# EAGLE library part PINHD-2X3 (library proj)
2mm PIN HEADER
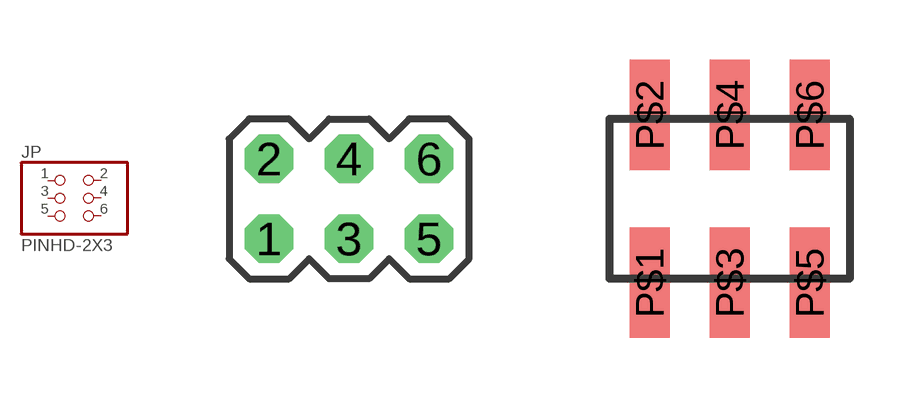
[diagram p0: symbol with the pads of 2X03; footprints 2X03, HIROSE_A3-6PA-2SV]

Designator prefix JP

## PINHD-2X3THRU  [2X03]
1  1  pas
2  2  pas
3  3  pas
4  4  pas
5  5  pas
6  6  pas

## PINHD-2X3SMT  [HIROSE_A3-6PA-2SV]
P$1  1  pas
P$2  2  pas
P$3  3  pas
P$4  4  pas
P$5  5  pas
P$6  6  pas

## Footprint 2X03 (pad centres in mm)
2mm PIN HEADER
drill 0.7 octagon: 1 -2,-1; 2 -2,1; 3 0,-1; 4 0,1; 5 2,-1; 6 2,1

## Footprint HIROSE_A3-6PA-2SV (pad centres in mm)
smd 1 x 2.75: P$1 -2,-2.1; P$2 -2,2.1; P$3 0,-2.1; P$4 0,2.1; P$5 2,-2.1; P$6 2,2.1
